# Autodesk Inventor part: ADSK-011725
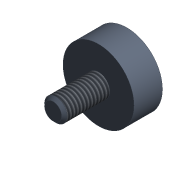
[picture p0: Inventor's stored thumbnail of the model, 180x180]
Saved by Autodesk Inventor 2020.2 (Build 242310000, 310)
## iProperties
Created: 2000-03
Part Number: ADSK-011725
Material: Plomb
Description: SHOCK-ABSORBER,PAD,STUD MOUNT, 5/16-18
Document SubType Name: Modeling
Designer: sspink
Density: 11.37 g/cm^3
Appearance: Métal - Plomb
Mass: 64.8257 g
Surface Area: 21.5325 cm^2
Volume: 5.70147 cm^3
Control State: 0
Master: False
Checked Out: False
Shininess: 10.0
Length Units: 11269
Angle Units: 11279
Time Units: 11290
Mass Units: 11283
Length Display Precision: 3
Angle Display Precision: 2
Compacted: True
Cutlength: 23.25
Material Desc: Material Description goes here
Material_Number: Pearson
Dimensions: 25x26x25 mm
Mass: 0,065 kg
VLT_Material: Lead
Density: 11.37
Volumn: 4.826388738403666
Area: 17.73476176841242
PropertySet Name: Model Information
Author: sspink
Revision Number: -
Title: SHOCK-ABSORBER,PAD,STUD MOUNT, 5/16-18
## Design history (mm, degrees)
node "Solide1"
  node "Extrusion1" dims "d1" = 10, "d2" = 0
  node "Extrusion2" dims "d4" = 16, "d5" = 0
sketch "Sketch1"
  geometry: C1 r 12.5 at (0, 0); 1 further point
  constraints: 1 centre point, 1 coincident
  dimensions: "d0" = 25 diameter of C1
sketch "Sketch2"
  geometry: C1 r 12.5 at (0, 0) reference; C2 r 4 at (0, 0)
  constraints: 1 centre point, 1 coincident
  dimensions: "d3" = 8 diameter of C2
feature "Gewinde1" dims "d6" = 16, "d7" = 0
chamfer "Fase1" distance "d8" = 1; stored, may be unused: second distance "d9" = 2, angle "d10" = 45 deg
node "Corps solides"
node "Corps surfaciques"
